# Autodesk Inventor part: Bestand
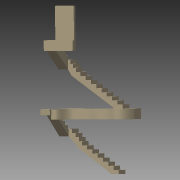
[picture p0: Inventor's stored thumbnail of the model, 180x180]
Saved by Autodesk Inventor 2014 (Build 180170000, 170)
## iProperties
Created: 2013-09
Part Number: Bestand
Material: Glasfaserbeton
Document SubType Name: Modeling
Designer: Stefan Tammegger
Density: 1.7 g/cm^3
Appearance: Beige
Mass: 5.64338e+06 g
Surface Area: 353465 cm^2
Volume: 3.31963e+06 cm^3
Author: Stefan Tammegger
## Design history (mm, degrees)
sketch "Skizze1"
  geometry: L1 (-460, 0)-(0, 0); L2 (0, 0)-(0, 178); L3 (0, 178)-(-280, 178); L4 (-280, 178)-(-280, 358); L5 (-280, 358)-(-560, 358); L6 (-560, 358)-(-560, 536); L7 (-560, 536)-(-840, 536); L8 (-840, 536)-(-840, 713); L9 (-840, 713)-(-1120, 713); L10 (-1120, 713)-(-1120, 895); L11 (-1120, 895)-(-1400, 895); L12 (-1400, 895)-(-1400, 1074); L13 (-1400, 1074)-(-1680, 1074); L14 (-1680, 1074)-(-1680, 1253); L15 (-1680, 1253)-(-1955, 1253); L16 (-1955, 1253)-(-1955, 1433); L17 (-1955, 1433)-(-2110, 1433); L18 (-2110, 1433)-(-2110, 1613); L19 (-2110, 1613)-(-2275, 1613); L20 (-2275, 1613)-(-2275, 1790); L21 (-2275, 1790)-(-2470, 1790); L22 (-2470, 1790)-(-2470, 1971); L23 (-2470, 1971)-(-2650, 1971); L24 (-1400, 1074)-(0, 178); L25 (-2094.805, 1103.132)-(-460, 56.857); L26 (-460, 0)-(-460, 56.857); L27 (-2650, 1971)-(-2650, 1651); L28 (-2094.805, 1103.132)-(-2650, 1651); 1 further point
  constraints: 56 end point, 13 parallel, 11 perpendicular, 1 horizontal
  dimensions: "d0" = 178 distance of L1.end L2.end; "d1" = 280 distance of L2.end L3.end; "d2" = 180 distance of L3.end L4.end; "d3" = 280 distance of L4.end L5.end; "d4" = 178 distance of L5.end L6.end; "d5" = 280 distance of L6.end L7.end; "d6" = 177 distance of L7.end L8.end; "d7" = 280 distance of L8.end L9.end; "d9" = 182 distance of L9.end L10.end; "d10" = 280 distance of L10.end L11.end; "d11" = 179 distance of L11.end L12.end; "d12" = 280 distance of L12.end L13.end; "d13" = 179 distance of L13.end L14.end; "d14" = 275 distance of L14.end L15.end; "d15" = 180 distance of L15.end L16.end; "d16" = 155 distance of L16.end L17.end; "d17" = 180 distance of L17.end L18.end; "d18" = 165 distance of L18.end L19.end; "d19" = 177 distance of L19.end L20.end; "d20" = 195 distance of L20.end L21.end; "d21" = 181 distance of L21.end L22.end; "d22" = 180 distance of L23.end L22.end; "d25" = 0 distance of L1.end point (0, 0); "d26" = 0 distance from line of point (0, 0) L2; "d29" = 460 distance of L1.start L1.end; "d30" = 350 distance between parallel lines of L25 L24; "d51" = 320 distance of L23.end L27.end; "d53" = 780 distance of L25.start L27.end
extrude "Extrusion1" new body sketch "Skizze1" distance "d34" = 500; taper "d35" = 0 deg
workplane "Arbeitsebene1"
feature "Trennen1"
workplane "Arbeitsebene5"
  workplane "Arbeitsebene4"
sketch "Skizze2"
  geometry: L1 (0, -4.712)-(320, -4.712); L2 (0, -4.712)-(0, -446.079); L3 (0, -4.712)-(0, 61.288); L4 (0, 61.288)-(-179, 61.288); L5 (-179, 61.288)-(-179, 289.288); L6 (-179, 289.288)-(-355, 289.288); L7 (-355, 289.288)-(-355, 457.288); L8 (-355, 457.288)-(-535, 457.288); L9 (-535, 457.288)-(-535, 625.288); L10 (-535, 625.288)-(-713, 625.288); L11 (-713, 625.288)-(-713, 793.288); L12 (-713, 793.288)-(-890, 793.288); L13 (-890, 793.288)-(-890, 1463.867); L14 (320, -4.712)-(0, -4.712) reference; L15 (320, -4.712)-(-624, 967.17); L16 (-624, 967.17)-(-624, 1443.029); L17 (-624, 1443.029)-(-890, 1463.867); 1 further point
  constraints: 32 end point, 7 perpendicular, 5 parallel, 1 collinear, 1 horizontal, 1 point on line
  dimensions: "d41" = 66 distance of L1.start L3.end; "d42" = 179 distance of L3.end L4.end; "d43" = 228 distance of L4.end L5.end; "d44" = 176 distance of L5.end L6.end; "d45" = 168 distance of L6.end L7.end; "d46" = 180 distance of L7.end L8.end; "d47" = 168 distance of L8.end L9.end; "d48" = 178 distance of L9.end L10.end; "d49" = 168 distance of L10.end L11.end; "d50" = 177 distance of L11.end L12.end; "d54" = 0 distance from line of L14 L1.start
extrude "Extrusion2" new body sketch "Skizze2" distance "d55" = 500; taper "d56" = 0 deg
sketch "Skizze3"
  geometry: L1 (-0.062, -0.002)-(-499.89, -13.09) reference; L2 (0, 500)-(-499.89, -13.09); L3 (-0.062, -0.002)-(0, 500); 1 further point
  constraints: 4 end point
extrude "Extrusion3" join sketch "Skizze3" distance "d57" = 320; taper "d58" = 0 deg
sketch "Skizze4"
  geometry: L1 (0, 0)-(-500, 0) reference; L2 (13.15, 565.829)-(-500, 66) reference; L3 (0.062, 66)-(180, 61.288) reference; L4 (-262.8, 297.042)-(-500, 66); L5 (-500, 0)-(-500, 66); L6 (0, 0)-(-262.8, 297.042); 1 further point
  constraints: 6 end point, 1 collinear, 1 point on line
  dimensions: "d60" = 133 deg angle of L3 L6
extrude "Extrusion4" join sketch "Skizze4" stored distance "d61" = 320; taper "d62" = 0 deg
workplane "Arbeitsebene6"
sketch "Skizze5"
  geometry: L1 (0, 670.579)-(-500, 670.579) reference; L2 (0, 670.579)-(0, 0) reference; L3 (3499.586, 1408.153)-(-30, 1500.579); L4 (-30, 1500.579)-(-30, 670.579); L5 (-30, 670.579)-(-30, 137.758); L6 (3499.586, 1408.153)-(3374.61, 863.304); L7 (3374.61, 863.304)-(2942.396, 630.937); L8 (2942.396, 630.937)-(2649.154, 878.476); L9 (2649.154, 878.476)-(2177.885, 878.476); L10 (2177.885, 878.476)-(1876.714, 802.392); L11 (1876.714, 802.392)-(1369.113, 984.788); L12 (1369.113, 984.788)-(957.046, 773.779); L13 (957.046, 773.779)-(570.579, 879.745); L14 (570.579, 879.745)-(341.996, 404.169); L15 (341.996, 404.169)-(272.194, 59.474); L16 (272.194, 59.474)-(-30, 137.758); 1 further point
  constraints: 6 end point, 1 parallel, 3 other
  dimensions: "d67" = 30 distance between parallel lines of L4 L2; "d68" = 830 distance of L3.end L4.end; "d69" = 88.5 deg angle of L4 L3
extrude "Extrusion5" new body sketch "Skizze5" distance "d70" = 461; taper "d71" = 0 deg
sketch "Skizze7"
  geometry: L1 (3530.796, 0)-(3530.796, -461) reference; L2 (577.796, 0)-(577.796, 179); L3 (577.796, 179)-(860.796, 179); L4 (860.796, 179)-(860.796, 358); L5 (860.796, 358)-(1143.796, 358); L6 (1143.796, 358)-(1143.796, 533); L7 (1143.796, 533)-(1424.796, 533); L8 (1424.796, 533)-(1424.796, 708); L9 (1424.796, 708)-(1703.796, 708); L10 (1703.796, 708)-(1703.796, 887); L11 (1703.796, 887)-(1984.796, 887); L12 (1984.796, 887)-(1984.796, 1063); L13 (1984.796, 1063)-(2267.796, 1063); L14 (2267.796, 1063)-(2267.796, 1238); L15 (2267.796, 1238)-(2544.796, 1238); L16 (2544.796, 1238)-(2544.796, 1415); L17 (2544.796, 1415)-(2824.796, 1415); L18 (2824.796, 1415)-(2824.796, 1591); L19 (2824.796, 1591)-(3053.796, 1591); L20 (3053.796, 1591)-(3053.796, 1771); L21 (3053.796, 1771)-(3217.796, 1771); L22 (3217.796, 1771)-(3217.796, 1945); L23 (3217.796, 1945)-(3352.796, 1945); L24 (3352.796, 1945)-(3352.796, 2122); L25 (3352.796, 2122)-(3482.796, 2122); L26 (3482.796, 2122)-(3482.796, 1712); L27 (577.796, 0)-(1082.796, 0); L28 (1082.796, 0)-(1082.796, 45.251); L29 (1082.796, 45.251)-(3292.754, 1430.071); L30 (3292.754, 1430.071)-(3482.796, 1712); 1 further point
  constraints: 58 end point, 15 perpendicular, 11 parallel, 1 coincident
  dimensions: "d79" = 179 distance of L2.start L2.end; "d80" = 283 distance of L2.end L3.end; "d81" = 179 distance of L3.end L4.end; "d82" = 283 distance of L4.end L5.end; "d83" = 175 distance of L5.end L6.end; "d84" = 281 distance of L6.end L7.end; "d85" = 175 distance of L7.end L8.end; "d86" = 279 distance of L8.end L9.end; "d87" = 179 distance of L9.end L10.end; "d88" = 281 distance of L10.end L11.end; "d89" = 176 distance of L11.end L12.end; "d90" = 283 distance of L12.end L13.end; "d91" = 175 distance of L13.end L14.end; "d92" = 277 distance of L14.end L15.end; "d93" = 177 distance of L15.end L16.end; "d94" = 280 distance of L16.end L17.end; "d95" = 176 distance of L17.end L18.end; "d96" = 229 distance of L18.end L19.end; "d97" = 180 distance of L19.end L20.end; "d98" = 164 distance of L20.end L21.end; "d99" = 174 distance of L21.end L22.end; "d100" = 135 distance of L22.end L23.end; "d101" = 177 distance of L23.end L24.end; "d102" = 130 distance of L24.end L25.end; "d103" = 410 distance of L25.end L26.end; "d104" = 505 distance of L2.start L27.end; "d106" = 380 distance from line of L29 L8.end; "d108" = 340 distance of L29.end L30.end; "d109" = 2953 distance between parallel lines of L2 L1
workplane "Arbeitsebene7"
sketch "Skizze8"
  geometry: L1 (1984.796, 1063)-(2267.796, 1063); L2 (2267.796, 1063)-(2267.796, 1238); L3 (2267.796, 1238)-(2544.796, 1238); L4 (1082.796, 45.251)-(3292.754, 1430.071); L5 (2544.796, 1238)-(2544.796, 1415); L6 (2544.796, 1415)-(2824.796, 1415); L7 (2824.796, 1591)-(3053.796, 1591); L8 (2824.796, 1415)-(2824.796, 1591); L9 (1984.796, 887)-(1984.796, 1063); L10 (1703.796, 887)-(1984.796, 887); L11 (3053.796, 1591)-(3053.796, 1771); L12 (3053.796, 1771)-(3217.796, 1771); L13 (3292.754, 1430.071)-(3482.796, 1712); L14 (3217.796, 1771)-(3217.796, 1945); L15 (3217.796, 1945)-(3352.796, 1945); L16 (3482.796, 2122)-(3482.796, 1712); L17 (3352.796, 2122)-(3482.796, 2122); L18 (3352.796, 1945)-(3352.796, 2122); L19 (577.796, 0)-(577.796, 179); L20 (577.796, 179)-(860.796, 179); L21 (860.796, 179)-(860.796, 358); L22 (860.796, 358)-(1143.796, 358); L23 (1082.796, 0)-(1082.796, 45.251); L24 (577.796, 0)-(1082.796, 0); L25 (1424.796, 533)-(1424.796, 708); L26 (1424.796, 708)-(1703.796, 708); L27 (1703.796, 708)-(1703.796, 887); L28 (1143.796, 533)-(1424.796, 533); L29 (1143.796, 358)-(1143.796, 533); L30 (3530.796, 0)-(3530.796, -461) reference; 1 further point
  constraints: 58 end point, 15 perpendicular, 10 parallel
  dimensions: "d111" = 179 distance of L19.start L19.end; "d112" = 283 distance of L19.end L20.end; "d113" = 179 distance of L20.end L21.end; "d114" = 283 distance of L21.end L22.end; "d115" = 175 distance of L22.end L28.start; "d116" = 281 distance of L28.start L25.start; "d117" = 175 distance of L25.start L25.end; "d118" = 279 distance of L25.end L26.end; "d119" = 179 distance of L26.end L10.start; "d120" = 281 distance of L10.start L9.start; "d121" = 176 distance of L9.start L1.start; "d122" = 283 distance of L1.start L1.end; "d123" = 175 distance of L1.end L2.end; "d124" = 277 distance of L2.end L3.end; "d125" = 177 distance of L3.end L5.end; "d126" = 280 distance of L5.end L6.end; "d127" = 176 distance of L6.end L7.start; "d128" = 229 distance of L7.start L7.end; "d129" = 180 distance of L7.end L11.end; "d130" = 164 distance of L11.end L12.end; "d131" = 174 distance of L12.end L14.end; "d132" = 135 distance of L14.end L15.end; "d133" = 177 distance of L15.end L17.start; "d134" = 130 distance of L17.start L16.start; "d135" = 410 distance of L16.start L13.end; "d136" = 505 distance of L19.start L23.start; "d137" = 380 distance from line of L4 L25.end; "d138" = 340 distance of L13.end L4.end; "d139" = 2953 distance between parallel lines of L30 L19
extrude "Extrusion6" new body sketch "Skizze8" distance "d140" = 500; taper "d141" = 0 deg
sketch "Skizze9"
  geometry: L1 (3530.796, -461)-(0, -461) reference; L2 (1082.796, 0)-(1082.796, 45.251) reference; L3 (0, 0)-(1082.796, 0); L4 (1082.796, 0)-(1082.796, -461); L5 (1082.796, -461)-(0, -461); L6 (0, -461)-(0, 0); 1 further point
  constraints: 8 end point, 2 parallel, 1 horizontal, 1 perpendicular, 1 point on line
extrude "Extrusion7" join sketch "Skizze9" distance "d142" = 500; taper "d143" = 0 deg
workplane "Arbeitsebene8"
sketch "Skizze10"
  geometry: L1 (410, 0)-(410, 499.951) reference; L2 (0, 0)-(410, 0) reference; L3 (585, 0)-(585, -150); L4 (585, -150)-(761, -150); L5 (761, -150)-(761, -312); L6 (761, -312)-(938, -312); L7 (938, -312)-(938, -517); L8 (938, -517)-(1113, -517); L9 (1113, -517)-(1113, -777); L10 (1113, -777)-(1288, -777); L11 (1288, -777)-(1288, -1083.196); L12 (585, 0)-(0, 0); L13 (0, 0)-(979.91, -1083.196); L14 (979.91, -1083.196)-(1288, -1083.196); 1 further point
  constraints: 24 end point, 4 parallel, 3 perpendicular, 1 collinear
  dimensions: "d146" = 150 distance of L3.start L3.end; "d147" = 176 distance of L3.end L4.end; "d148" = 162 distance of L4.end L5.end; "d149" = 177 distance of L5.end L6.end; "d150" = 205 distance of L6.end L7.end; "d151" = 175 distance of L7.end L8.end; "d153" = 175 distance of L9.end L10.end; "d155" = 260 distance of L8.end L9.end
extrude "Extrusion8" new body sketch "Skizze10" distance "d156" = 500; taper "d157" = 0 deg
workplane "Arbeitsebene11"
  workplane "Arbeitsebene10"
sketch "Skizze11"
  geometry: L1 (1113, -108.137)-(1288, -108.137) reference; L2 (1288, -108.137)-(1288, -603.272) reference; L3 (828, -106.05)-(828, 797.666); L4 (1288, -106.05)-(1288, 797.666); L5 (828, 797.666)-(1288, 797.666); L6 (828, -106.05)-(1288, -106.05); 1 further point
  constraints: 8 end point, 2 parallel, 1 perpendicular
  dimensions: "d161" = 460 distance between parallel lines of L3 L2; "d162" = 460 distance between parallel lines of L3 L4
extrude "Extrusion9" join sketch "Skizze11" distance "d163" = 300; taper "d164" = 0 deg
sketch "Skizze12"
  geometry: L1 (0, 460)-(0, 0) reference; L2 (0, 0)-(300, 0) reference; L3 (0, 460)-(300, 460); L4 (300, 460)-(300, 0); L5 (300, 0)-(0, 0); L6 (0, 0)-(0, 460); 1 further point
  constraints: 8 end point, 2 parallel, 1 horizontal, 1 perpendicular
extrude "Extrusion10" join sketch "Skizze12" distance "d165" = 500; taper "d166" = 0 deg
sketch "Skizze13"
  geometry: L1 (1404.025, 75.994)-(500, -51.059) reference; L2 (1404.025, 75.994)-(500, -51.059); L3 (1424.901, -72.546)-(520.876, -199.599); L4 (500, -51.059)-(520.876, -199.599); L5 (1404.025, 75.994)-(1424.901, -72.546); 1 further point
  constraints: 8 end point, 3 equal length, 1 perpendicular
  dimensions: "d167" = 150 distance between parallel lines of L3 L1
extrude "Extrusion11" join sketch "Skizze13" distance "d168" = 1500; taper "d169" = 0 deg
sketch "Skizze14"
  geometry: L1 (0, 150)-(-500, 150) reference; L2 (0, 150)-(129.987, 148.185) reference; L3 (0, 150)-(-443.273, 543.556); L4 (-443.273, 543.556)-(-500, 150); L5 (0, 150)-(-500, 150); 1 further point
  constraints: 6 end point, 1 collinear
  dimensions: "d170" = 139.2 deg angle of L3 L2
extrude "Extrusion12" join sketch "Skizze14" stored distance "d171" = 2000; taper "d172" = 0 deg
sketch "Skizze15"
  geometry: L1 (218.871, 331.963)-(0, 0) reference; L2 (218.871, 331.963)-(592.771, 0) reference; L3 (218.871, 331.963)-(0, 0); L4 (592.771, 0)-(266.06, -378.498) reference; L5 (0, 0)-(266.06, -378.498); L6 (592.771, 0)-(592.771, 0); L7 (592.771, 0)-(218.871, 331.963); L8 (592.771, 0)-(266.06, -378.498); 1 further point
  constraints: 10 end point, 3 collinear, 1 perpendicular, 1 point on line, 1 other
extrude "Extrusion13" join sketch "Skizze15" distance "d173" = 250; taper "d174" = 0 deg
feature "Kombinieren1"
  node "Volumenkörper4"
feature "Kombinieren2"
  node "Volumenkörper1"
node "Volumenkörper2"
node "Volumenkörper3"
node "Volumenkörper5"
other parameters: "d36" = 0, "d39" = 88.5 deg, "d63" = 0, "d110" = -55, "d144" = -15.56834, "d159" = 98 deg
